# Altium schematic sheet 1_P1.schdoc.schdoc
size 309 x 223 mm; Symbol: Sheet-Symbol_A4; Device: Sheet-Symbol_A4; Company: 嘉立创EDA; Version: V1.0; Page Size: A4; @Project Name: buck电路; @Page Count: 1; @Update Date: 2024-04-19; @Create Date: 2024-04-19; @Schematic Name: Schematic1; @Page No: 1; @Page Name: P1
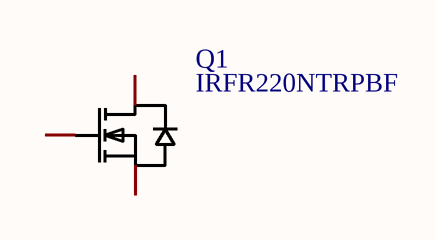
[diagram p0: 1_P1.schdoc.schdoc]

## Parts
Q1  IRFR220NTRPBF  [TO-252-2_L6.6-W6.1-P4.57-LS9.9-TR-CW]

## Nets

Not connected (* = marked no-connect by the designer): Q1 1(G) 2(D) 3(S)

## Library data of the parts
Q1 = IRFR220NTRPBF: Manufacturer: Infineon(英飞凌); Add into BOM: yes; Type: 1个N沟道; Drain Source Voltage (Vdss): 200V; Continuous Drain Current (Id): 5A; Power Dissipation (Pd): 43W; Drain Source On Resistance (RDS(on)@Vgs,Id): 600mΩ@10V,2.9A; Gate Threshold Voltage (Vgs(th)@Id): 4V@250uA; Total Gate Charge (Qg@Vgs): 23nC@10V; Input Capacitance (Ciss@Vds): 300pF@25V; Description: 类型:1个N沟道;漏源电压(Vdss):200V;连续漏极电流(Id):5A;功率(Pd):43W;导通电阻(RDS(on)@Vgs,Id):600mΩ@10V,2.9A;阈值电压(Vgs(th)@Id):4V@250uA;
